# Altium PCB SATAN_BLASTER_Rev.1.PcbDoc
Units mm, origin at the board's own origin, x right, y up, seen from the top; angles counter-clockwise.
Board outline 60 x 40 mm, 2 copper layers (Top Layer, Bottom Layer), stack 1.571 mm thick; 57 components, 65 nets, 296 pads, 67 vias.
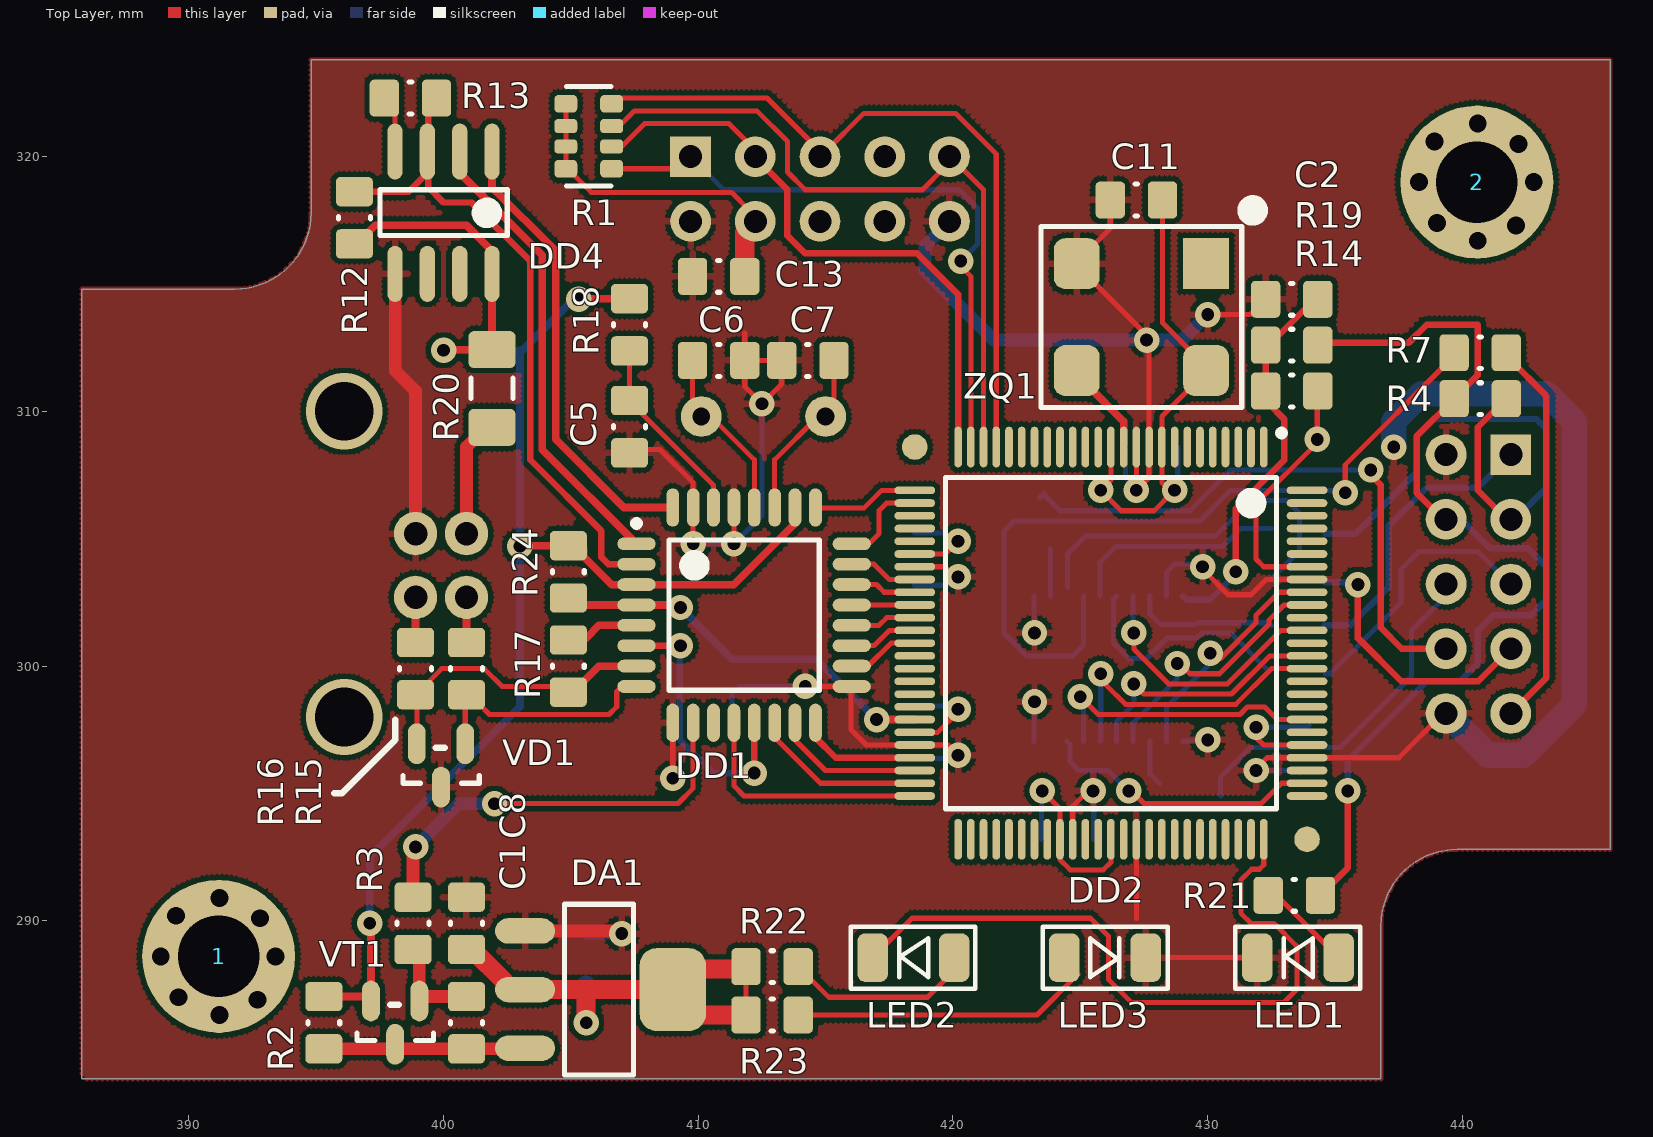
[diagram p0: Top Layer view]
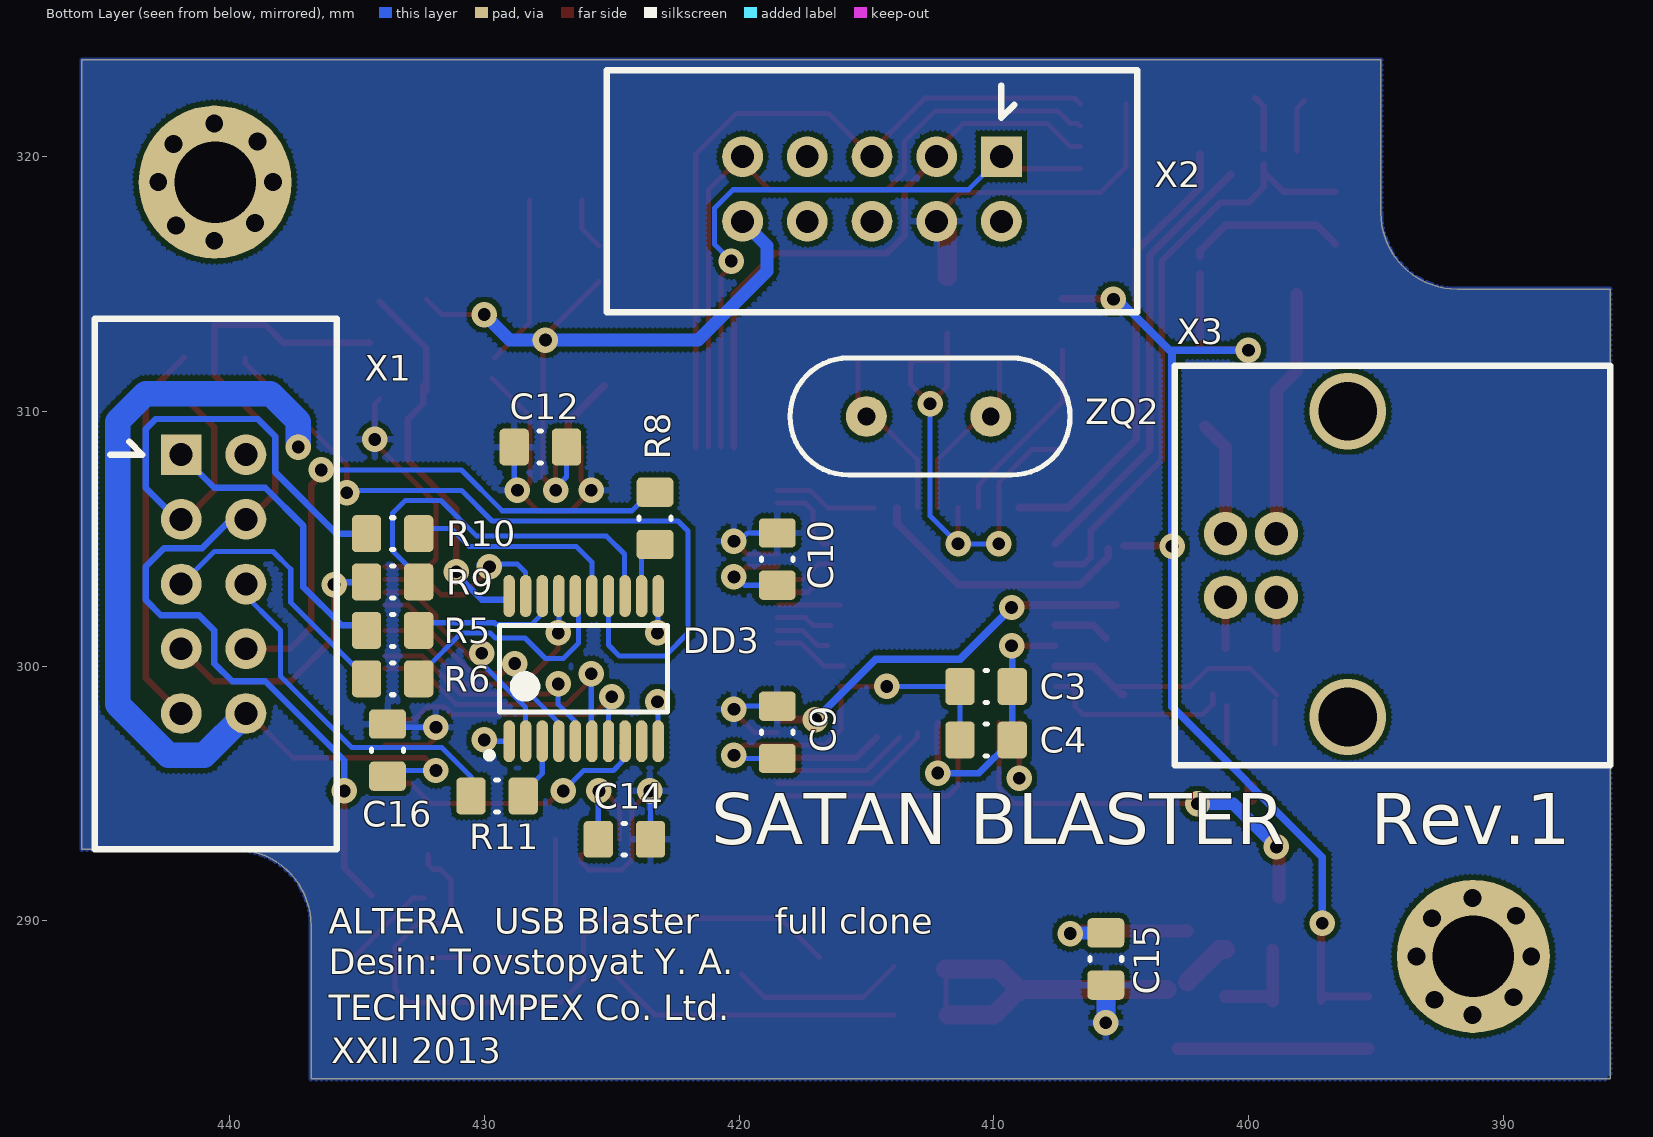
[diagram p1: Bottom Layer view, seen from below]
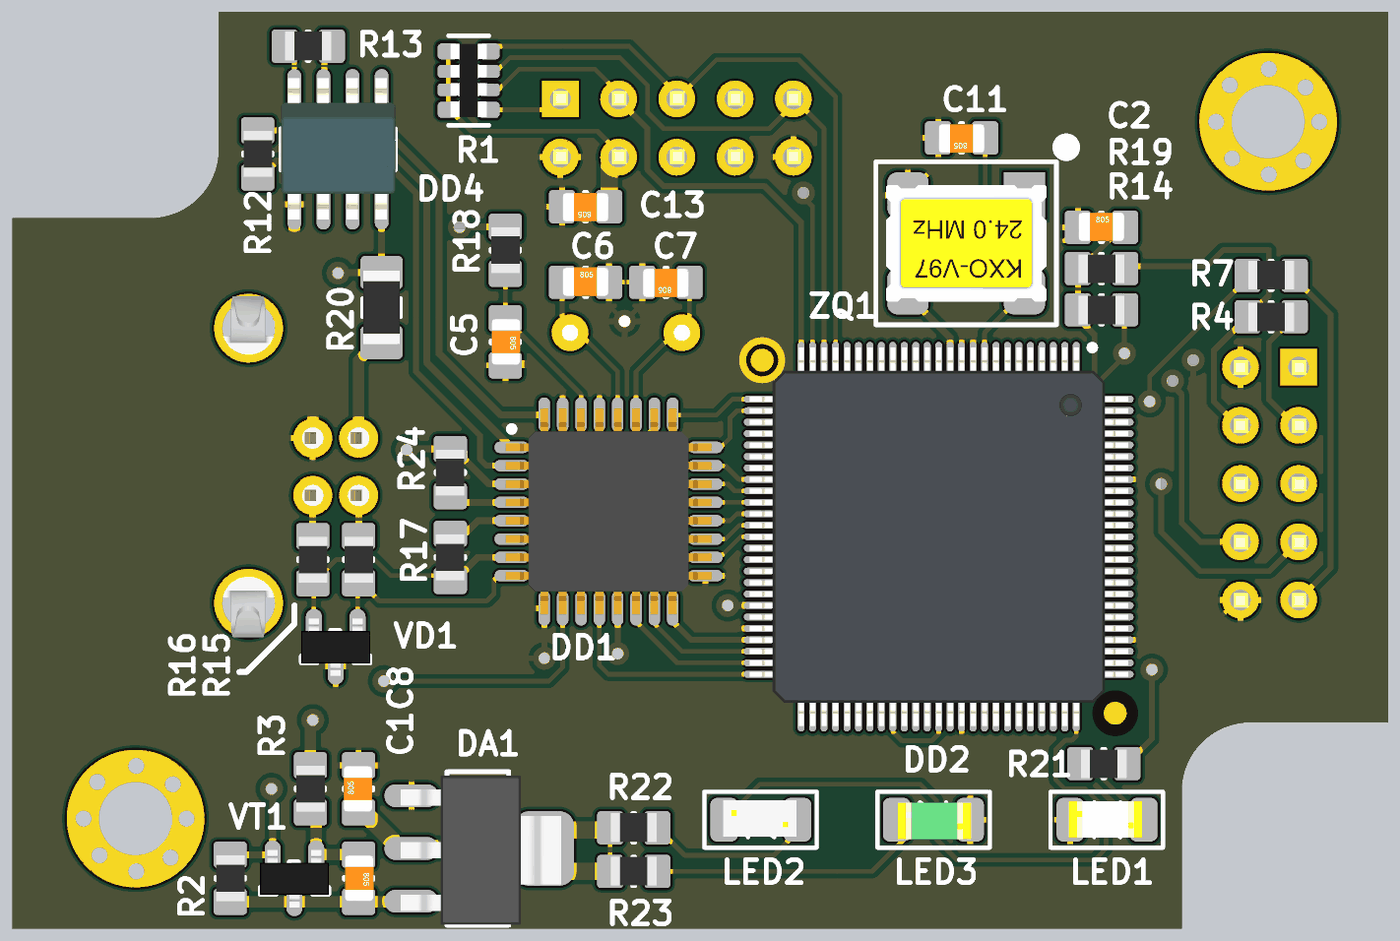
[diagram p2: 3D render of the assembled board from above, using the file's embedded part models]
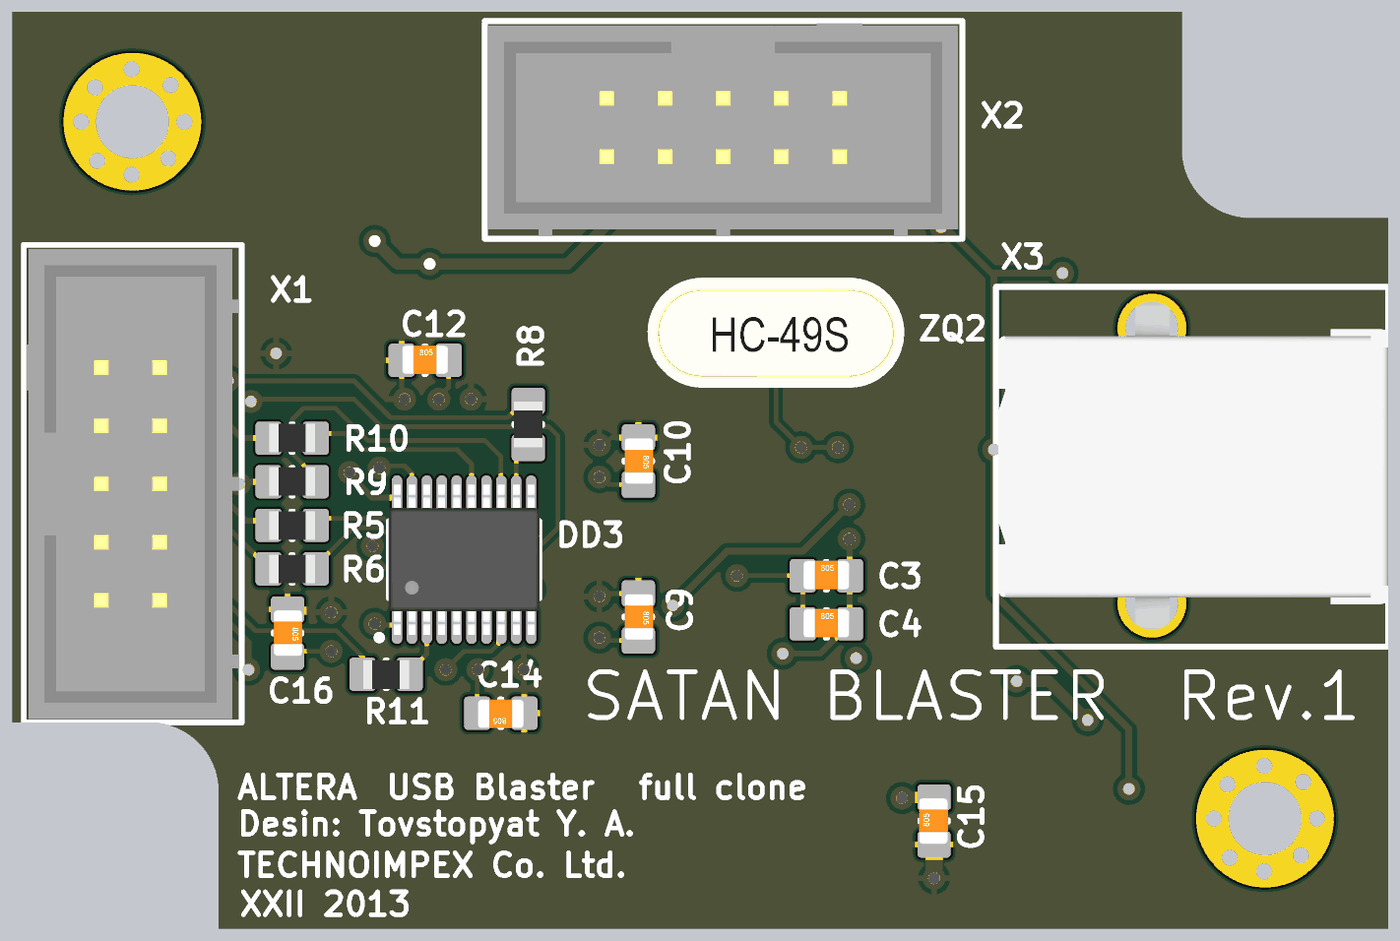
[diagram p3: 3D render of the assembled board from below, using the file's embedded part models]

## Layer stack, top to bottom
Top Solder: solder mask 0.0102, Solder Resist, Dk 3.5
Top Layer: signal copper 0.0356
Dielectric1: core 1.5, FR-4, Dk 4.8
Bottom Layer: signal copper 0.0356
Bottom Solder: solder mask 0.0102, Solder Resist, Dk 3.5

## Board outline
385.8,283.8 385.8,314.8 391.8,314.8 ccw(c391.8,317.8) 394.8,317.8 394.8,323.8 445.8,323.8 445.8,292.8 439.8,292.8 ccw(c439.8,289.8) 436.8,289.8 436.8,283.8

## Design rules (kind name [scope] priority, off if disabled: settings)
Clearance [All] p1: gap=0.2
HoleSize [All] p1: absolutevalues=TRUE maxlimit=10 minlimit=0.5 maxpercent=80.000 minpercent=20.000
MinimumSolderMaskSliver MinimumSolderMaskSliver_1 [InComponent('1','2')] p1: minsoldermaskwidth=0
MinimumSolderMaskSliver [All] p2: minsoldermaskwidth=0.05
PolygonConnect [All] p1: connectstyle=Relief reliefconductorwidth=0.254 reliefentries=4 polygonreliefangle="90 Angle" airgapwidth=0.254
RoutingVias [All] p1: holewidth=0.5 width=1.27 viastyle="Through Hole" minholewidth=0.5 minwidth=1 maxholewidth=10 maxwidth=10
ShortCircuit ShortCircuit_1 [InComponent('1','2')] p1: allowed=TRUE
ShortCircuit [All] p2: allowed=FALSE
SilkToSilkClearance [All] p1: silktosilkclearance=0.1
SilkToSolderMaskClearance SilkscreenOverComponentPads [IsPad] p1: minsilkscreentomaskgap=0.1 clearancetoexposedcopper=TRUE
SolderMaskExpansion [All] p1: expansion=0.102
Width [All] p1: maxlimit=2 minlimit=0.2 preferedwidth=0.2
24 further rules are at their usual default settings.

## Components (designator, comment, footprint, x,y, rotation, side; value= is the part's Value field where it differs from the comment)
1 "M3" M3 391.2,288.6 r90 top
2 "M3" M3 440.6,319 r90 top
C1 "100нФ  10%  50В 0805 X7R" C0805 400.9,286 r270 top
C2 "470нФ 10% 50 В" C0805 433.3,314.4 r0 top
C3 "4.7нФ  5%  25В 0805 NPO" C0805 410.3,299.2 r180 bottom
C4 "470нФ 10% 50 В" C0805 410.3,297.1 r180 bottom
C5 "100нФ  10%  50В 0805 X7R" C0805 407.3,309.4 r270 top
C6 "27пФ  5%  50В 0805 NPO" C0805 410.8,312 r0 top
C7 "27пФ  5%  50В 0805 NPO" C0805 414.3,312 r180 top
C8 "470нФ 10% 50 В" C0805 400.9,289.9 r90 top
C9 "470нФ 10% 50 В" C0805 418.5,297.4 r270 bottom
C10 "470нФ 10% 50 В" C0805 418.5,304.2 r270 bottom
C11 "470нФ 10% 50 В" C0805 427.2,318.3 r180 top
C12 "470нФ 10% 50 В" C0805 427.8,308.6 r180 bottom
C13 "470нФ 10% 50 В" C0805 410.8,315.3 r180 top
C14 "470нФ 10% 50 В" C0805 424.5,293.2 r0 bottom
C15 "470нФ 10% 50 В" C0805 405.6,288.5 r90 bottom
C16 "470нФ 10% 50 В" C0805 433.8,296.7 r270 bottom
DA1 "LD1117S33TR" SOT-223 406.1,287.3 r270 top
DD1 "FT245BM" LQFP-32-P0.8 411.8,302 r0 top
DD2 "EPM240T100C5" TQFP-100 426.2,300.9 r270 top
DD3 "74LVC244APWR" TSSOP-20 426.1,299.9 r90 bottom
DD4 "93LC46" SO-8 400,317.8 r270 top
LED1 "GNL-1206UWC" LED1206W 433.6,288.608 r180 top
LED2 "LHN974-Z" LED1206R 418.5,288.608 r180 top
LED3 "LGN971-Z" LED1206G 425.912,288.5 r0 top
R1 "2.2 кОм 4D03" 4D03 405.7,320.8 r180 top
R2 "0 Ом 0805 5%" R0805 395.3,286 r270 top
R3 "1.0 кОм 0805 5%" R0805 398.8,289.9 r270 top
R4 "10 кОм 0805 5%" R0805 440.7,310.5 r180 top
R5 "51 Ом 0805 5%" R0805 433.6,301.4 r0 bottom
R6 "51 Ом 0805 5%" R0805 433.6,299.5 r0 bottom
R7 "51 Ом 0805 5%" R0805 440.7,312.3 r0 top
R8 "51 Ом 0805 5%" R0805 423.3,305.8 r90 bottom
R9 "51 Ом 0805 5%" R0805 433.6,303.3 r180 bottom
R10 "51 Ом 0805 5%" R0805 433.6,305.2 r180 bottom
R11 "51 Ом 0805 5%" R0805 429.5,294.9 r0 bottom
R12 "10 кОм 0805 5%" R0805 396.5,317.6 r270 top
R13 "2.2 кОм 0805 5%" R0805 398.7,322.3 r0 top
R14 "0 Ом 0805 5%" R0805 433.3,310.8 r180 top
R15 "20 Ом 0805 5%" R0805 400.9,299.9 r270 top
R16 "20 Ом 0805 5%" R0805 398.9,299.9 r270 top
R17 "1.5 кОм 0805 5%" R0805 404.9,300 r90 top
R18 "470 Ом 0805 5%" R0805 407.3,313.4 r270 top
R19 "0 Ом 0805 5%" R0805 433.3,312.6 r180 top
R20 "0 Ом 1206 5%" R1206 401.9,310.9 r90 top
R21 "1.0 кОм 0805 5%" R0805 433.4,291 r180 top
R22 "1.0 кОм 0805 5%" R0805 412.9,288.2 r0 top
R23 "1.0 кОм 0805 5%" R0805 412.9,286.3 r0 top
R24 "100 кОм 0805 5%" R0805 404.9,303.7 r90 top
VD1 "MMBZ5V6ALT1G" SOT-23 399.9,296.1 r270 top
VT1 "IRLML5103" SOT-23 398.1,286 r270 top
X1 "BH-10" BH-10 441.9,308.3 r270 bottom
X2 "BH-10" BH-10 409.7,320 r0 bottom
X3 "USB-B" USB-B 400.8,304 r90 bottom
ZQ1 "KXO-V97 24.0 MHz" KXO-97 427.4,313.7 r180 top
ZQ2 "HC-49S 6.00 MHz" HC-49S 415,309.8 r180 bottom

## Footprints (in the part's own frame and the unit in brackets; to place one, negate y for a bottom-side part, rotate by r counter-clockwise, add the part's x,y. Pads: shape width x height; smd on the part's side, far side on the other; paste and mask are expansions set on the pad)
4D03 [mm]
  rrect50% 0.9x0.7 smd mask+0.127: 1(-0.9,1.275) 4(-0.9,-1.275) 5(0.9,-1.275) 8(0.9,1.275)
  rrect50% 0.9x0.55 smd mask+0.127: 2(-0.9,0.4) 3(-0.9,-0.4) 6(0.9,-0.4) 7(0.9,0.4)
  silkscreen extent -0.87,-1.95 0.87,1.95, body extent -0.8,-1.6 0.8,1.6, height 0.6
BH-10 [mm]
  rect 1.6x1.6 hole 0.9: 1(0,0)
  round 1.6 hole 0.9: 2(0,2.54) 3(2.54,0) 4(2.54,2.54) 5(5.08,0) 6(5.08,2.54) 7(7.62,0) 8(7.62,2.54) 9(10.16,0) 10(10.16,2.54)
  silkscreen extent -5.33,-3.4 15.5,6.1, body extent -5.15,-3.3 15.35,6, height 9.1
C0805 [mm]
  rrect30% 1.15x1.45 smd: 1(-1.025,0) 2(1.025,0)
  silkscreen extent -0.05,-0.63 0.05,0.62, body extent -1,-0.6 1,0.65, height 0.78
HC-49S [mm]
  round 1.6 hole 0.7: 1(0,0) 2(4.88,0)
  silkscreen extent -3,-2.3 8,2.3, body extent -3.09,-2.35 8.09,2.3, height 3.71
KXO-97 [mm]
  rect 1.8x2 smd: 1(-2.54,-2.1)
  rrect50% 1.8x2 smd: 2(2.54,-2.1) 3(2.54,2.1) 4(-2.54,2.1)
  silkscreen extent -4.66,-4.49 3.94,3.56, body extent -3.5,-2.54 3.5,2.54, height 1.81
LED1206G [mm]
  rrect50% 1.2x1.9 smd: 1(-1.544,0.054) 2(1.656,0.054)
  silkscreen extent -2.38,-1.17 2.52,1.27, body extent -1.5,-0.8 1.7,0.8, height 1.11
LED1206R [mm]
  rrect50% 1.2x1.9 smd: 1(-1.544,0.054) 2(1.656,0.054)
  silkscreen extent -2.38,-1.17 2.52,1.27, body extent -1.5,-0.8 1.7,0.8, height 1.11
LED1206W [mm]
  rrect50% 1.2x1.9 smd: 1(-1.544,0.054) 2(1.656,0.054)
  silkscreen extent -2.38,-1.17 2.52,1.27, body extent -1.47,-0.76 1.73,0.84, height 1.11
LQFP-32-P0.8 [mm]
  oval 1.5x0.5 smd: 1(-4.225,2.8) 2(-4.225,2) 3(-4.225,1.2) 4(-4.225,0.4) 5(-4.225,-0.4) 6(-4.225,-1.2) 7(-4.225,-2) 8(-4.225,-2.8) 17(4.225,-2.8) 18(4.225,-2) 19(4.225,-1.2) 20(4.225,-0.4) 21(4.225,0.4) 22(4.225,1.2) 23(4.225,2) 24(4.225,2.8)
  oval 0.5x1.5 smd: 9(-2.8,-4.225) 10(-2,-4.225) 11(-1.2,-4.225) 12(-0.4,-4.225) 13(0.4,-4.225) 14(1.2,-4.225) 15(2,-4.225) 16(2.8,-4.225) 25(2.8,4.225) 26(2,4.225) 27(1.2,4.225) 28(0.4,4.225) 29(-0.4,4.225) 30(-1.2,4.225) 31(-2,4.225) 32(-2.8,4.225)
  silkscreen extent -4.35,-2.95 2.95,3.72, body extent -4.5,-4.5 4.5,4.5, height 1.6
M3 [mm]
  round 6 hole 3.2: 0(0.003,0.031)
  body extent -3,-3 3,3, height 0.1
R0805 [mm]
  rrect30% 1.15x1.45 smd: 1(-1.025,0) 2(1.025,0)
  silkscreen extent -0.05,-0.62 0.05,0.62, body extent -1,-0.62 1,0.64, height 0.41
R1206 [mm]
  rrect30% 1.45x1.85 smd: 1(-1.525,0) 2(1.525,0)
  silkscreen extent -0.4,-0.82 0.4,0.82, body extent -1.6,-0.8 1.6,0.8, height 0.55
SO-8 [mm] "SOIC, 8-Leads, Body 5,0x4,0mm (max), Pitch 1,27mm, IPC Medium Density"
  oval 2.2x0.6 smd: 1(-2.4,1.905) 2(-2.4,0.635) 3(-2.4,-0.635) 4(-2.4,-1.905) 5(2.4,-1.905) 6(2.4,-0.635) 7(2.4,0.635) 8(2.4,1.905)
  silkscreen extent -0.9,-2.5 0.9,2.5, body extent -3.1,-2.49 3.05,2.51, height 1.75
SOT-23 [mm]
  oval 1.6x0.7 smd: 1(-0.85,0.95) 2(-0.85,-0.95) 3(0.85,0)
  silkscreen extent -0.7,-1.5 0.7,1.5, body extent -1.23,-1.5 1.27,1.5, height 1.05
SOT-223 [mm]
  oval 1x2.35 smd: 1(-2.3,-2.9) 2(0,-2.9) 3(2.3,-2.9)
  rrect50% 3.25x2.6 smd: 2(0,2.9)
  silkscreen extent -3.35,-1.35 3.35,1.35, body extent -3.18,-3.37 3.33,3.63, height 1.69
TQFP-100 [mm]
  oval 1.6x0.3 smd: 1(-7.7,6) 2(-7.7,5.5) 3(-7.7,5) 4(-7.7,4.5) 5(-7.7,4) 6(-7.7,3.5) 7(-7.7,3) 8(-7.7,2.5) 9(-7.7,2) 10(-7.7,1.5) 11(-7.7,1) 12(-7.7,0.5) 13(-7.7,0) 14(-7.7,-0.5) 15(-7.7,-1) 16(-7.7,-1.5) 17(-7.7,-2) 18(-7.7,-2.5) 19(-7.7,-3) 20(-7.7,-3.5) 21(-7.7,-4) 22(-7.7,-4.5) 23(-7.7,-5) 24(-7.7,-5.5) 25(-7.7,-6) 51(7.7,-6) 52(7.7,-5.5) 53(7.7,-5) 54(7.7,-4.5) 55(7.7,-4) 56(7.7,-3.5) 57(7.7,-3) 58(7.7,-2.5) 59(7.7,-2) 60(7.7,-1.5) 61(7.7,-1) 62(7.7,-0.5) 63(7.7,0) 64(7.7,0.5) 65(7.7,1) 66(7.7,1.5) 67(7.7,2) 68(7.7,2.5) 69(7.7,3) 70(7.7,3.5) 71(7.7,4) 72(7.7,4.5) 73(7.7,5) 74(7.7,5.5) 75(7.7,6)
  oval 0.3x1.6 smd: 26(-6,-7.7) 27(-5.5,-7.7) 28(-5,-7.7) 29(-4.5,-7.7) 30(-4,-7.7) 31(-3.5,-7.7) 32(-3,-7.7) 33(-2.5,-7.7) 34(-2,-7.7) 35(-1.5,-7.7) 36(-1,-7.7) 37(-0.5,-7.7) 38(0,-7.7) 39(0.5,-7.7) 40(1,-7.7) 41(1.5,-7.7) 42(2,-7.7) 43(2.5,-7.7) 44(3,-7.7) 45(3.5,-7.7) 46(4,-7.7) 47(4.5,-7.7) 48(5,-7.7) 49(5.5,-7.7) 50(6,-7.7) 76(6,7.7) 77(5.5,7.7) 78(5,7.7) 79(4.5,7.7) 80(4,7.7) 81(3.5,7.7) 82(3,7.7) 83(2.5,7.7) 84(2,7.7) 85(1.5,7.7) 86(1,7.7) 87(0.5,7.7) 88(0,7.7) 89(-0.5,7.7) 90(-1,7.7) 91(-1.5,7.7) 92(-2,7.7) 93(-2.5,7.7) 94(-3,7.7) 95(-3.5,7.7) 96(-4,7.7) 97(-4.5,7.7) 98(-5,7.7) 99(-5.5,7.7) 100(-6,7.7)
  round 1 smd paste-25.4 mask+0.5: 101(-7.7,-7.7) 102(7.7,7.7)
  silkscreen extent -8.37,-6.5 6.5,6.82, body extent -8.25,-8.25 8.26,8.26, height 1.75
TSSOP-20 [mm]
  oval 1.65x0.45 smd: 1(-2.85,2.925) 2(-2.85,2.275) 3(-2.85,1.625) 4(-2.85,0.975) 5(-2.85,0.325) 6(-2.85,-0.325) 7(-2.85,-0.975) 8(-2.85,-1.625) 9(-2.85,-2.275) 10(-2.85,-2.925) 11(2.85,-2.925) 12(2.85,-2.275) 13(2.85,-1.625) 14(2.85,-0.975) 15(2.85,-0.325) 16(2.85,0.325) 17(2.85,0.975) 18(2.85,1.625) 19(2.85,2.275) 20(2.85,2.925)
  silkscreen extent -3.52,-3.3 1.7,3.83, body extent -3.28,-3.3 3.27,3.3, height 1.2
USB-B [mm]
  round 1.7 hole 0.92: 1(1.2,0.1) 2(-1.3,0.1) 3(-1.3,-1.9) 4(1.2,-1.9)
  silkscreen extent -7.9,-15 7.8,2.1, body extent -7.48,-15 7.4,2, height 11

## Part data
C1 C5: library part "100нФ  50В", "конденсатор керамический"
C2 C4 C8 C9 C10 C11 C12 C13 C14 C15 C16: library part "470нФ 50 В", "конденсатор керамический SMD"
C3: library part "4.7нФ  25В", "конденсатор керамический"
C6 C7: library part "27пФ  50В", "конденсатор керамический"
DA1: "Positive 3.3V SOT-223"
DD1: "FT245R USB FIFO"
DD2: "MAX II 3.3/2.5V CPLD, 80 IOs, 240 Logic Elements, 100-Pin Plastic TQFP, Commercial Temperature, Speed Grade 5"
DD3: "8-ми разрядный буфер"
DD4: "Serial EEPROM"
LED1: "Белый светодиод"
LED2: "Красный светодиод Uvd - 1.84 В"
LED3: "Зеленый светодиод Uvd - 2.2 В"
R1: "Массив резисторов"
R2 R3 R4 R5 R6 R7 R8 R9 R10 R11 R12 R13 R14 R15 R16 R17 R18 R19 R20 R21 R22 R23 R24: "резистор постоянный"
VD1: "Сдвоенный сапрессор"
VT1: "HEXFET Power MOSFET"
X1 X2: "вилка IDC на плату прямая"
X3: "USB Fimale connector type B"
ZQ1: "Кварцевый генератор"
ZQ2: "Кварцевый резонатор"

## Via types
v1: diameter 1, hole 0.5, Top Layer to Bottom Layer, tented both sides, 49 vias
v2: diameter 1.4, hole 0.7, Top Layer to Bottom Layer, 16 vias
v3: diameter 3, hole 2.3, Top Layer to Bottom Layer, 2 vias

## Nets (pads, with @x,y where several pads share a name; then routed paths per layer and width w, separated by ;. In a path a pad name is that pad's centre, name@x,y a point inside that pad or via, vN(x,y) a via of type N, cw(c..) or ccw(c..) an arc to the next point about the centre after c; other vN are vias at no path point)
AS_DATA_OUT: R9.1 X1.7 | length 10.5
  Top Layer w0.254: v1@435.9,303.3 v1(435.9,303.2) 435.9,301.1 437.6,299.4 440.62,299.4 X1.7
  Bottom Layer w0.254: R9.1 v1@435.7,303.3
AS_NCE: R11.2 X1.6 | length 13.9
  Bottom Layer w0.2: R11.2 430.5,294.925 430.5,295.631 431.668,296.799 435.199,296.799 438,299.6 438,301.4 X1.6@439.6,303
AS_NCS: R8.2 X1.8 | length 23.3
  Top Layer w0.254: v1@436.3,307.6 436.8,307.1 436.8,301.5 437.62,300.68 X1.8
  Bottom Layer w0.2: R8.2@423.4,306.6 423.6,306.8 423.6,306.7 424.2,306.1 429.3,306.1 430.9,307.7 v1(436.4,307.7)
AVCC: C5.1 DD1.30 R18.2 | length 7.5
  Top Layer w0.2: R18.2@407.3,312.4 C5.1 407.3,310.4 410.6,307.1 DD1.30
CLK0: DD2.12 ZQ1.3 | length 3
  Top Layer w0.3: ZQ1.3@425.3,311 426.7,309.6 DD2.12
CPLD_STATUS_LED: DD2.75 LED2.2 | length 27.2
  Top Layer w0.2: LED2.2 418.39,290.1 425.4,290.1 426.1,289.4 426.1,287.7 427,286.8 433,286.8 433.5,287.3 433.5,289 432.6,289.9 431.7,289.9 431.3,290.3 431.3,291.6 431.725,292.025 432.025,292.025 432.2,292.2 DD2.75@432.2,292.6
D0: DD1.25 DD2.26 | length 4.1
  Top Layer w0.2: DD1.25@414.7,306.2 416.5,306.2 417.2,306.9 DD2.26
D1: DD1.24 DD2.27 | length 3.2
  Top Layer w0.2: DD1.24@416.5,304.8 416.7,304.8 417.1,305.2 417.1,306.1 417.4,306.4 DD2.27
D2: DD1.23 DD2.33 | length 2.3
  Top Layer w0.2: DD1.23@416.4,304 416.9,304 417.5,303.4 DD2.33
D3: DD1.22 DD2.34 | length 2.1
  Top Layer w0.2: DD1.22@416.5,303.2 417,303.2 417.3,302.9 DD2.34
D4: DD1.21 DD2.35 | length 2.4
  Top Layer w0.2: DD1.21 DD2.35@418.45,302.4
D5: DD1.20 DD2.36 | length 2.2
  Top Layer w0.2: DD1.20@416.4,301.6 417.1,301.6 417.4,301.9 DD2.36
D6: DD1.19 DD2.37 | length 2.2
  Top Layer w0.2: DD1.19@416.5,300.8 416.9,300.8 417.5,301.4 DD2.37
D7: DD1.18 DD2.38 | length 3
  Top Layer w0.2: DD1.18@415.9,300 416.666,300 417.566,300.9 DD2.38
D+: DD1.7 R16.2 R17.1 VD1.2 | length 11.9
  Top Layer w0.2: R16.2 399.925,299.9 401.6,299.9 402.3,299.2 R17.1@405.3,299.2 ; VD1.2 R16.2@398.95,298.65
  Top Layer w0.3: R17.1@404.9,298.9 405,298.9 406.1,300 DD1.7
D-: DD1.8 R15.2 VD1.1 | length 9
  Top Layer w0.2: VD1.1 R15.2@400.85,298.45 ; R15.2@401.4,298.9 401.4,298.5 401.8,298.1 406.5,298.1 406.8,298.4 406.8,299 407,299.2 DD1.8
EPM_AS_DATA_OUT: DD2.82 DD3.7 | length 11
  Top Layer w0.2: v1(425,298.8) 425.701,298.099 431.268,298.099 431.568,298.399 432.231,298.399 432.73,297.9 DD2.82
  Bottom Layer w0.2: DD3.7 v1@425.125,298.575
EPM_AS_NCE: DD2.89 DD3.17 | length 10.4
  Top Layer w0.2: v1@427.1,301.4 427.1,300.669 428.469,299.299 430.771,299.299 432.871,301.4 DD2.89
  Bottom Layer w0.2: v1@427.075,301.275 DD3.17
  other v1: 427.1,301.3
EPM_AS_NCS: DD2.77 DD3.8 | length 11.1
  Top Layer w0.2: v1@427,295.1 427.5,294.6 432.1,294.6 432.9,295.4 DD2.77
  Bottom Layer w0.2: DD3.8 424.6,296.925 424.6,296.233 424.933,295.9 426.1,295.9 v1(426.9,295.1)
EPM_JTAG_TCK: DD2.92 DD3.2 | length 8.3
  Top Layer w0.2: v1@430.5,300.3 431.9,301.7 431.9,302 432.8,302.9 DD2.92
  Bottom Layer w0.2: DD3.2 428.375,298.375 430,300
  other v1: 430.099,300.499
EPM_JTAG_TDI: DD2.86 DD3.6 | length 11.9
  Top Layer w0.2: v1@426,299.7 426,299.269 426.769,298.499 431.102,298.499 432.503,299.9 DD2.86
  Bottom Layer w0.2: DD3.6 425.8,297.075 v1(425.8,299.7)
EPM_JTAG_TDO: DD2.87 DD3.5 | length 10.1
  Top Layer w0.2: v1(427.1,299.3) 427.501,298.899 430.936,298.899 432.437,300.4 DD2.87
  Bottom Layer w0.2: DD3.5 426.425,297.825 427.1,298.5 v1(427.1,299.3)
EPM_JTAG_TMS: DD2.91 DD3.4 | length 10.1
  Top Layer w0.2: v1@429,300 429.301,299.699 430.465,299.699 432.4,301.634 432.4,301.8 433,302.4 DD2.91
  Bottom Layer w0.2: DD3.4 427.075,297.775 428.8,299.5 428.8,299.9 v1@428.6,300.1
  other v1: 428.8,300.1
GND: C2.1 C3.1 C4.1 C5.2 C6.2 C7.2 C8.2 C9.2 C10.2 C11.2 C12.2 C13.2 C14.2 C15.2 C16.2 DA1.1 DD1.9 DD1.17 DD1.29 DD1.31 DD2.10 DD2.11 DD2.32 DD2.46 DD2.60 DD2.65 DD2.79 DD2.93 DD3.1 DD3.10 DD3.11 DD3.19 DD4.5 LED1.2 LED3.2 VD1.3 X1.2 X1.10 X2.2 X2.10 X3.4 ZQ1.2 | length 148.6
  Top Layer w0.2: C5.2@407.4,308.5 408.5,308.5 409.8,307.2 DD1.31 v1@409.8,304.9 ; v1@409,295.5 DD1.9 ; v1(411.4,304.8) DD1.29 ; 411.825,313.075 C6.2 ; v1@412.55,310.25 v1(412.5,310.3) 411.825,310.975 C6.2 ; v1@412.55,310.35 413.275,311.075 C7.2@413.275,311.825 ; C7.2 C7.2@413.275,311.825 ; v1(414.2,299.2) DD1.17 ; DD1.17@416,299.1 416,297.5 416.6,296.9 DD2.46 419.8,296.9 v1@420.4,296.3 ; DD2.32 419.7,303.9 v1@420.3,303.3 ; DD2.60 424.7,294.5 v1@425.4,295.2 ; ZQ1.2@425.5,315.1 427.7,312.9 DD2.10 427.7,307.4 v1(427.2,306.9) ; ZQ1.2@425.5,316.5 426.175,317.175 C11.2 ; v1@427,306.7 v1(427.2,306.9) ; 427.2,290.1 DD2.65 ; DD2.11 v1(427.2,306.9) ; 428.456,288.554 LED1.2 LED1.2@432.246,288.554 ; v1@429.9,303.7 430.8,302.8 431.7,302.8 432.3,303.4 DD2.93 ; v1(430,313.8) 431.675,313.8 C2.1 ; v1@431.9,296 431.931,296 432.331,296.4 DD2.79 437.5,296.4 X1.10@439.3,298.2 ; C6.2 413.1,312 C7.2@413.275,311.825
  Top Layer w0.5: DD4.5@398.1,314.6 398.1,311.6 398.9,310.8 X3.4 ; VD1.3@399.9,294.8 VD1.3 ; DA1.1@402.4,289.6 DA1.1 v1@406.9,289.6
  Bottom Layer w0.2: v1(409.8,304.8) v1@411.2,304.8 ; C4.1 C3.1@411.325,298.925 ; v1(411.4,304.8) 412.5,305.9 v1(412.5,310.3) ; C3.1@411.6,299.2 v1(414.2,299.2) ; C9.2 v1@420.325,296.375 ; C10.2 419.775,303.175 v1@420,303.4 ; DD3.10 v1@423.175,298.575 ; v1@423.175,301.325 DD3.11 ; C14.2 v1@425.525,295.025 ; C12.2 426.775,307.425 v1@427.1,307.1 ; DD3.19 428.375,303.675 428.7,304 v1@430.2,304 ; DD3.1 v1@429.95,297.05 ; v1(431.9,295.9) 433.5,295.9 C16.2@433.6,295.8
  Bottom Layer w0.5: C15.2 v1@406.925,289.525 ; X2.10 418.9,316.5 418.9,315.5 421.6,312.8 v1(427.6,312.8) 429,312.8 v1(430,313.8)
  Bottom Layer w1: v1@437.3,308.773 437.3,309.6 438.4,310.7 443.3,310.7 444.4,309.6 444.4,298.5 442.4,296.5 441,296.5 X1.10
  other v1: 407,289.5 425.5,295.1 409,295.6 420.2,296.5 430,297.1 423.2,298.6 423.2,301.3 420.2,303.5 429.8,303.9 437.3,308.6
JTAG_TCK: R5.2 X1.1 | length 11.5
  Bottom Layer w0.254: R5.2@434.6,301.6 435.6,301.6 437.1,303.1 437.1,305.5 438.6,307 440.6,307 X1.1
JTAG_TDI: R7.2 X1.9 | length 15.2
  Top Layer w0.254: R7.2@441.8,312.1 443.3,310.6 443.3,299.54 X1.9
JTAG_TDO: R4.1 R10.1 X1.3 | length 21.3
  Top Layer w0.254: R4.1 440.6,309.375 440.6,306.9 X1.3@441.8,305.7
  Bottom Layer w0.254: R10.1 435.8,305.2 438.2,307.6 438.2,309 438.9,309.7 442.9,309.7 443.3,309.3 443.3,307 X1.3@442.1,305.8
JTAG_TMS: R6.2 X1.5 | length 10.4
  Bottom Layer w0.2: R6.2@434.625,299.7 434.8,299.7 437.6,302.5 437.6,303.8 438.3,304.5 440.6,304.5 X1.5@441.8,303.3
NetC1_1: C1.1 R3.2 VT1.1 | length 3.7
  Top Layer w0.5: VT1.1 R3.2@399.05,288.85 ; VT1.1@399.175,287.025 C1.1
NetC1_2: C1.2 DA1.3 R2.2 VT1.3 | length 7.5
  Top Layer w0.5: R2.2 C1.2 DA1.3@402.775,284.975
NetC2_2: C2.2 DD3.20 R14.2 R19.2 | length 15.1
  Top Layer w0.254: v1(431.1,303.7) 431.1,306.175 433,308.075 433,309.7 432.4,310.3 R14.2@432.4,311 ; R14.2 432.275,312.475 C2.2@434.1,314.3
  Bottom Layer w0.254: DD3.20 429.175,302.6 430.1,302.6 v1@431.1,303.6
NetC6_1: C6.1 DD1.28 ZQ2.2 | length 6.7
  Top Layer w0.2: C6.1 409.775,310.425 ZQ2.2@410,310.2 ; ZQ2.2@410.1,310.2 412.2,308.1 DD1.28
NetC7_1: C7.1 DD1.27 ZQ2.1 | length 6.5
  Top Layer w0.2: DD1.27 413,308.1 ZQ2.1@414.7,309.8 ; ZQ2.1@414.8,310 415.325,310.525 C7.1
NetDD1_1: DD1.1 DD4.2 | length 17.3
  Top Layer w0.3: DD4.2@400.7,319.3 403.877,316.123 403.877,308.498 DD1.1
NetDD1_2: DD1.2 DD4.3 R12.1 R13.2 | length 25.5
  Top Layer w0.254: R12.1@396.6,318.625 398.625,318.625 DD4.3@399.3,319.3 ; DD4.3@399.4,319.7 399.4,318.8 400,318.2 401.1,318.2 403.4,315.9 403.4,308.1 406.2,305.3 406.2,304.275 406.475,304 DD1.2 ; DD4.3@399.4,320.3 399.4,321.975 R13.2
NetDD1_5: DD1.5 R17.2 | length 2.2
  Top Layer w0.3: R17.2@405.6,301.1 406.1,301.6 DD1.5
NetDD1_32: DD1.32 DD4.1 | length 17.9
  Top Layer w0.3: DD4.1@401.9,320.1 401.9,318.807 404.4,316.307 404.4,308.9 407.075,306.225 DD1.32
NetDD3_3: DD3.3 R11.1 | length 1.8
  Bottom Layer w0.2: DD3.3 427.725,295.775 R11.1@428.1,295.4
NetDD3_12: DD3.12 R8.1 | length 1.9
  Bottom Layer w0.2: DD3.12 R8.1@423.825,304.6
NetDD3_13: DD3.13 R9.2 | length 14.4
  Bottom Layer w0.2: DD3.13@424.5,303.1 424.5,304.4 425.2,305.1 430.3,305.1 431.7,306.5 433.1,306.5 433.6,306 433.6,304.525 R9.2@432.575,303.5
NetDD3_14: DD3.14 R7.1 | length 30.7
  Top Layer w0.2: v1(435.4,306.8) 435.4,307.9 439.4,311.9 R7.1@439.4,312.1
  Bottom Layer w0.2: DD3.14 425.125,300.825 424.7,300.4 422.9,300.4 422,301.3 422,305.3 422.4,305.7 429.7,305.7 430.9,306.9 v1@435.5,306.9
NetDD3_15: DD3.15 R10.2 | length 8.6
  Bottom Layer w0.2: DD3.15 425.775,304.075 426.4,304.7 430.6,304.7 431.3,305.4 R10.2@432.5,305.4
NetDD3_16: DD3.16 R6.1 | length 9.1
  Bottom Layer w0.2: DD3.16 426.3,302.625 426.3,300.9 426.9,300.3 427.6,300.3 428.4,301.1 429.568,301.1 429.768,301.299 430.901,301.299 R6.1@432.3,299.9
NetDD3_18: DD3.18 R5.1 | length 5.7
  Bottom Layer w0.2: DD3.18 427.725,302.058 428.158,301.625 429.528,301.625 429.602,301.699 432.401,301.699 R5.1@432.5,301.6
NetDD4_4: DD4.4 R13.1 | length 2.1
  Top Layer w0.2: R13.1@397.8,322.2 398.095,321.905 DD4.4
NetLED1_1: LED1.1 R21.2 | length 3.7
  Top Layer w0.2: R21.2@432.375,290.9 432.8,290.9 LED1.1@435.1,288.6
NetLED2_1: LED2.1 R22.2 | length 6.8
  Top Layer w0.2: R22.2 415.125,287 419,287 LED2.1@419.9,287.9
NetLED3_1: LED3.1 R23.2 | length 11.6
  Top Layer w0.2: R23.2 423.3,286.3 LED3.1@424.9,287.9
NetR15_1: R15.1 X3.2 | length 2
  Top Layer w0.3: R15.1@400.9,300.7 X3.2
NetR16_1: R16.1 X3.3 | length 2
  Top Layer w0.3: R16.1@398.9,300.7 X3.3
NetR20_1: R20.1 X3.1 | length 4.5
  Top Layer w0.5: X3.1 400.9,308.6 R20.1@401.7,309.4
PWR_EN: DD1.10 R3.1 | length 16.4
  Top Layer w0.2: v1(402,294.6) 409.2,294.6 409.8,295.2 DD1.10
  Top Layer w0.5: R3.1 v1@398.8,292.9
  Bottom Layer w0.5: v1(398.9,292.9) 400.6,294.6 v1(402,294.6)
TCK_C: DD2.24 R1.1 X2.1 | length 24.6
  Top Layer w0.2: R1.1 409.225,319.525 X2.1@409.5,319.8 ; v1@420.1,315.9 420.7,315.3 DD2.24
  Bottom Layer w0.2: X2.1@410,319.7 411,318.7 420.236,318.7 420.96,317.976 420.96,316.56 v1(420.3,315.9)
TDI_C: DD2.23 R1.3 X2.9 | length 27.6
  Top Layer w0.2: R1.3 406.7,321.3 407,321.3 407.5,321.8 412.3,321.8 413.5,320.6 413.5,319.4 414.2,318.7 418.8,318.7 X2.9@419.7,319.6 ; X2.9@419.9,320 421.2,318.7 DD2.23
TDO_C: DD2.25 R1.2 X2.3 | length 23.1
  Top Layer w0.2: R1.2 407,320.4 407.9,321.3 411.2,321.3 X2.3@412.2,320.3
  Top Layer w0.254: X2.3@412.6,319.6 413.5,318.7 413.5,316.9 414.2,316.2 418.6,316.2 420.2,314.6 DD2.25
TMS_C: DD2.22 R1.4 X2.5 | length 28.8
  Top Layer w0.2: R1.4 406.825,322.3 412.7,322.3 X2.5@414.9,320.1 ; X2.5@415,320.2 416.5,321.7 420.1,321.7 421.7,320.1 DD2.22
USB_RD: DD1.16 DD2.47 | length 4.2
  Top Layer w0.254: DD1.16@414.6,297.2 415.4,296.4 DD2.47
USB_RESET: DD1.4 DD2.44 R24.1 | length 15.2
  Top Layer w0.3: R24.1@405.2,302.4 DD1.4 v1@409.3,302.4 ; v1@416.9,297.9 v1(417,297.9) DD2.44
  Bottom Layer w0.3: v1(409.3,302.3) 411.325,300.275 414.625,300.275 v1(417,297.9)
USB_RW: DD1.15 DD2.48 | length 5.3
  Top Layer w0.2: DD1.15@413.7,297.2 415,295.9 DD2.48
USB_RX: DD1.12 DD2.50 | length 9.2
  Top Layer w0.2: DD1.12@411.4,297.2 411.4,295.3 411.8,294.9 DD2.50
USB_TX: DD1.14 DD2.49 | length 6.4
  Top Layer w0.2: DD1.14@413,297.4 413,297.2 414.8,295.4 DD2.49
VCC: DD1.3 DD1.26 DD4.8 R2.1 R12.2 R18.1 R20.2 R24.2 VT1.2 | length 61.8
  Top Layer w0.3: R2.1 VT1.2@397.025,287.025 ; R12.2@396.6,316.575 397.325,317.3 400.9,317.3 401.9,316.3 DD4.8@401.9,316.1 ; VT1.2 v1@397.15,289.95 ; v1@399.825,312.425 R20.2 DD4.8@401.9,315.4 ; v1@403.075,304.725 R24.2 ; v1@405.475,314.425 R18.1 ; R24.2@405.5,304.6 405.5,304.3 406.6,303.2 DD1.3 411.4,303.2 413.8,305.6 DD1.26@413.8,306.2
  Bottom Layer w0.3: v1(397.1,289.9) 397.1,292.5 403,298.4 403,312.4 ; v1(400,312.4) 403,312.4 ; v1@405.6,314.5 405.2,314.5 403.1,312.4 403,312.4
  other v1: 403,304.7 405.3,314.4
VCCIO: C8.1 C9.1 C10.1 C11.1 C12.1 C13.1 C14.1 C15.1 C16.1 DA1.2 DD2.9 DD2.13 DD2.31 DD2.45 DD2.59 DD2.63 DD2.80 DD2.94 R1.5 R1.6 R1.7 R1.8 R14.1 R22.1 R23.1 X2.4 ZQ1.4 | length 79.4
  Top Layer w0.2: R1.5 R1.6 R1.7 404.8,319.6 405.8,318.6 411.3,318.6 X2.4@412,317.9 ; R23.1 R22.1@411.875,288.075 ; DD2.45 419.4,297.4 v1@420.2,298.2 ; DD2.31 419.7,304.4 v1(420.2,304.9) v1@420.3,305 ; v1@423.4,295.2 v1(423.5,295.1) 424.2,294.4 DD2.59 424.2,292.4 424.6,292 425.9,292 426.2,292.3 DD2.63@426.2,292.6 ; DD2.13 426.2,307.3 v1(425.8,306.9) 426.6,306.1 427.9,306.1 v1@428.6,306.8 ; C11.1 428.225,313.475 ZQ1.4@429.6,312.1 ; v1@428.7,306.7 v1@428.6,306.8 ; v1(428.7,306.9) v1@428.6,306.8 ; ZQ1.4@429.7,311.3 428.2,309.8 DD2.9 428.2,307.2 v1@428.6,306.8 ; v1@431.9,297.2 432.2,296.9 DD2.80 ; DD2.94 432.2,303.9 431.9,304.2 431.9,306.372 434.3,308.772 v1(434.3,308.9) 434.3,310.3 R14.1@434.1,310.5
  Top Layer w0.75: C8.1 401.125,288.875 DA1.2@402.4,287.6 ; DA1.2@403.2,287.3 408.9,287.3 DA1.2@409,287.2 ; v1(405.6,286) 405.6,287.1 ; R23.1@411.8,286.3 410,286.3 409,287.3 409.8,288.1 R22.1@411.9,288.1 ; C13.1 411.825,317.025 X2.4@412.2,317.4
  Bottom Layer w0.2: C9.1 v1@420.175,298.425 ; C10.1 419.675,305.225 v1@420,304.9 ; C14.1 v1@423.475,295.075 ; v1@428.825,307.025 C12.1 ; v1(431.899,297.599) 433.899,297.599 C16.1@434,297.7
  Bottom Layer w0.75: v1@405.6,285.9 v1(405.6,286) C15.1
  other v1: 420.2,298.3
VCCIO_USB: C3.2 C4.2 DD1.6 DD1.13 | length 10.8
  Top Layer w0.254: DD1.6 v1@409.4,300.8 ; DD1.13 412.2,296.1 v1@412.3,296
  Bottom Layer w0.254: v1@409.275,300.825 C3.2 C4.2 410.575,295.8 v1(412.2,295.8)
  other v1: 409.3,300.8
VTREF: R4.2 R19.1 R21.1 X1.4 | length 38.4
  Top Layer w0.254: R21.1 435.5,292.075 v1(435.5,295.1) v1@435.5,295.2 ; R19.1@434.5,312.7 437.9,312.7 438.6,313.4 440.6,313.4 440.6,311.425 R4.2 438.2,309.025 438.2,306.8 X1.4@439.2,305.8
  Bottom Layer w0.254: v1(435.5,295.1) 435.5,296.3 438.6,299.4 439.9,299.4 440.6,300.1 440.6,301.4 441.2,302 442.7,302 443.3,302.6 443.3,303.9 442.567,304.633 441.071,304.633 439.944,305.76 X1.4
pads on no net: 1.0 2.0 DD1.11 DD2.1 DD2.2 DD2.3 DD2.4 DD2.5 DD2.6 DD2.7 DD2.8 DD2.14 DD2.15 DD2.16 DD2.17 DD2.18 DD2.19 DD2.20 DD2.21 DD2.28 DD2.29 DD2.30 DD2.39 DD2.40 DD2.41 DD2.42 DD2.43 DD2.51 DD2.52 DD2.53 DD2.54 DD2.55 DD2.56 DD2.57 DD2.58 DD2.61 DD2.62 DD2.64 DD2.66 DD2.67 DD2.68 DD2.69 DD2.70 DD2.71 DD2.72 DD2.73 DD2.74 DD2.76 DD2.78 DD2.81 DD2.83 DD2.84 DD2.85 DD2.88 DD2.90 DD2.95 DD2.96 DD2.97 DD2.98 DD2.99 DD2.100 DD2.101 DD2.102 DD3.9 DD4.6 DD4.7 X2.6 X2.7 X2.8 ZQ1.1
copper on no net:
  other v2: 391.2,286.3 392.7,286.9 389.6,287 388.9,288.6 393.4,288.6 392.8,290.1 389.5,290.2 391.2,290.9 440.6,316.7 442.1,317.3 439,317.4 438.3,319 442.8,319 442.2,320.5 438.9,320.6 440.6,321.3
  other v3: 396.1,298 396.1,310

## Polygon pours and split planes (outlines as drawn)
VCCIO on Bottom Layer "Top Layer-No Net" (hatched 90Degree grid 0.2 track 0.2, remove dead copper, pour order 4): 385.8,283.8 385.8,314.8 391.8,314.8 ccw(c391.8,317.8) 394.8,317.8 394.8,323.8 445.8,323.8 445.8,292.8 439.8,292.8 ccw(c439.8,289.8) 436.8,289.8 436.8,283.8
GND on Top Layer "Top Layer-No Net" (hatched 90Degree grid 0.2 track 0.2, remove dead copper, pour order 2): 385.8,283.8 385.8,314.8 391.8,314.8 ccw(c391.8,317.8) 394.8,317.8 394.8,323.8 445.8,323.8 445.8,292.8 439.8,292.8 ccw(c439.8,289.8) 436.8,289.8 436.8,283.8

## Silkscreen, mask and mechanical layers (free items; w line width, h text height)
Top Overlay:
  lines w0.254: 395.7,295 396,295 398.1,297.1 398.1,297.9
Bottom Overlay:
  text "Rev.1" at 395.2,293 h2
  text "SATAN BLASTER" at 421.1,293 h2
  text "full clone" at 418.6,289.5 h1
  text "USB Blaster" at 429.6,289.5 h1
  text "ALTERA" at 436.1,289.5 h1
  text "Desin: Tovstopyat Y. A." at 436.1,287.9 h1
  text "TECHNOIMPEX Co. Ltd." at 436.1,286.1 h1
  text "XXII 2013" at 436,284.4 h1
Mechanical 2:
  the board outline again, w0.254

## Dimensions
394.8,323.8 to 385.8,283.8 on Mechanical 1
385.8,283.8 to 445.8,292.8 on Mechanical 1
440.569,319.003 to 391.169,288.603 on Mechanical 1
440.569,319.003 to 391.169,288.603 on Mechanical 1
